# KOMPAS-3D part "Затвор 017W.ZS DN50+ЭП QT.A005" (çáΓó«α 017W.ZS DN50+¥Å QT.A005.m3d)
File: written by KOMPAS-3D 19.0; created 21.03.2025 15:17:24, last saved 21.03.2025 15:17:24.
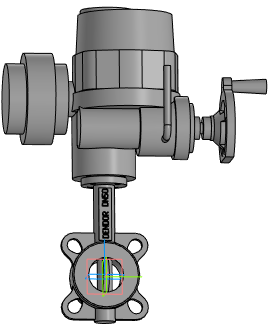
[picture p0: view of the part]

Document properties: Полное имя файла: Затвор 017W.ZS DN50+ЭП QT.A005.a3d

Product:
- Part/product: Затвор 017W.ZS DN50+ЭП QT.A005
    Масса: 38.8915

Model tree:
1. Операция без истории:1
